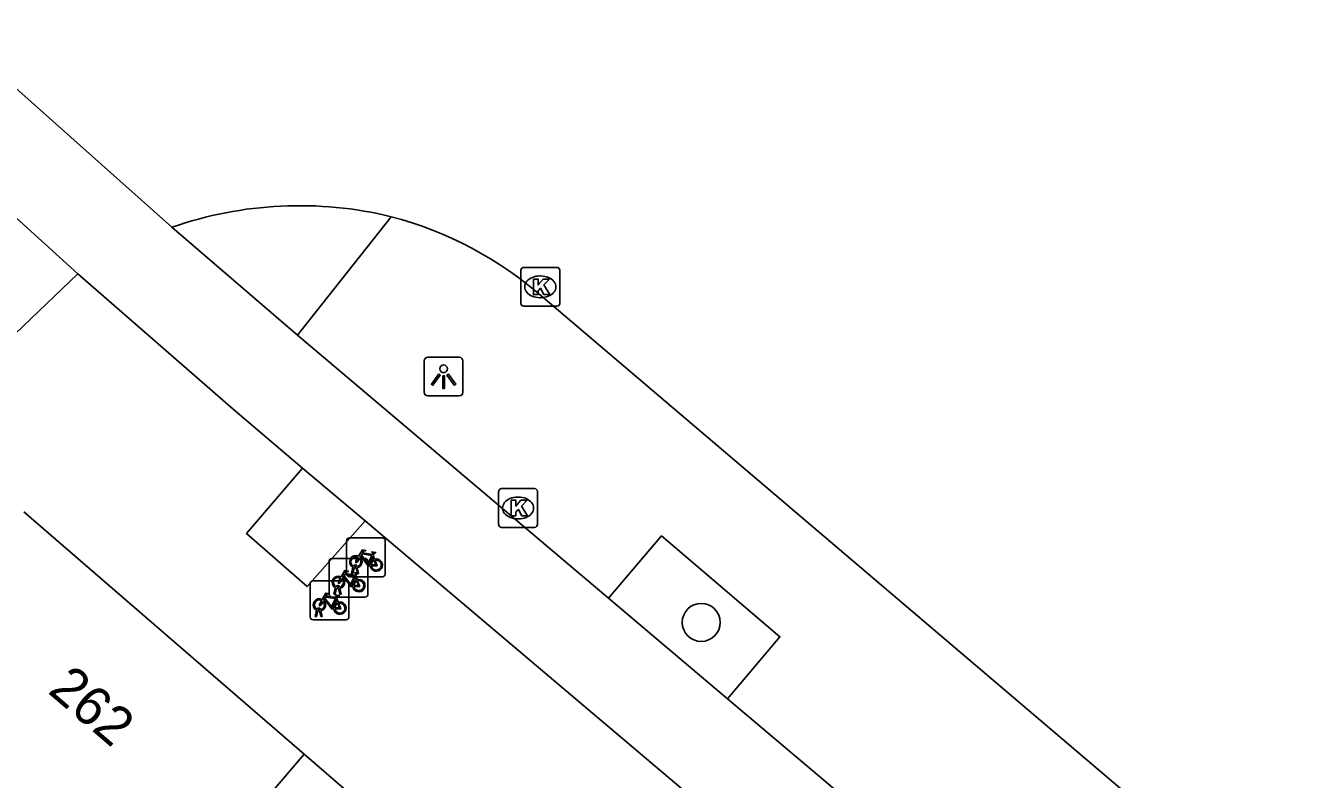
# Model space of a CAD drawing. Extents: x 162347 to 162868, y 381221 to 381813.
# Drawn here: x 162687 to 162719.68, y 381648.06 to 381667.49 of the extents above; entities that cross this region are included whole.
import ezdxf

# ---------------------------------------------------------------- set-up
doc = ezdxf.new("R2010")
doc.units = 0
for name, color, linetype in [('IMGEO_Berm_open', 7, 'Continuous'), ('IMGEO_Boom', 7, 'Continuous'), ('IMGEO_Fietsenrek', 7, 'Continuous'), ('IMGEO_Fietspad_gesloten', 7, 'Continuous'), ('IMGEO_Kolk', 7, 'Continuous'), ('IMGEO_Lichtpunt', 7, 'Continuous'), ('IMGEO_Pand', 7, 'Continuous'), ('IMGEO_Pand_nummerreeks', 7, 'Continuous'), ('IMGEO_Rijbaan_lokaal_gesloten', 7, 'Continuous'), ('IMGEO_Voetpad_open', 7, 'Continuous')]:
    doc.layers.add(name, color=color, linetype=linetype)

msp = doc.modelspace()

# ---------------------------------------------------------------- linework, layer by layer
at = {"layer": 'IMGEO_Berm_open'}
for points in [[(162696.427, 381662.56), (162694.013, 381659.509)], [(162702.028, 381652.737), (162703.396, 381654.339), (162706.444, 381651.742), (162705.095, 381650.146)]]:
    msp.add_lwpolyline(points, dxfattribs=at)
at = {"layer": 'IMGEO_Boom'}
msp.add_circle((162704.417, 381652.111), 0.489, dxfattribs=at)
at = {"layer": 'IMGEO_Fietsenrek'}
for p, q in [((162695.276, 381653.363), (162695.276, 381654.204)), ((162695.276, 381654.204), (162695.276, 381653.363)), ((162695.351, 381654.288), (162696.192, 381654.288)), ((162696.192, 381654.288), (162695.351, 381654.288)), ((162696.276, 381654.213), (162696.276, 381653.372)), ((162696.276, 381653.372), (162696.276, 381654.213)), ((162694.826, 381652.833), (162694.826, 381653.674)), ((162694.826, 381653.674), (162694.826, 381652.833)), ((162694.901, 381653.758), (162695.742, 381653.758)), ((162695.742, 381653.758), (162694.901, 381653.758)), ((162695.403, 381653.372), (162695.442, 381653.532)), ((162695.514, 381653.544), (162695.513, 381653.548)), ((162695.545, 381653.555), (162695.546, 381653.548)), ((162695.826, 381653.683), (162695.826, 381652.842)), ((162695.826, 381652.842), (162695.826, 381653.683)), ((162695.963, 381653.837), (162695.999, 381653.742)), ((162696.201, 381653.288), (162695.36, 381653.288)), ((162695.36, 381653.288), (162696.201, 381653.288)), ((162695.437, 381653.372), (162695.403, 381653.372)), ((162695.472, 381653.52), (162695.437, 381653.372)), ((162695.513, 381653.307), (162695.549, 381653.212)), ((162695.555, 381653.372), (162695.521, 381653.514)), ((162695.553, 381653.518), (162695.588, 381653.372)), ((162695.588, 381653.372), (162695.555, 381653.372)), ((162694.338, 381652.253), (162694.338, 381653.094)), ((162694.338, 381653.094), (162694.338, 381652.253)), ((162694.413, 381653.178), (162695.254, 381653.178)), ((162695.254, 381653.178), (162694.413, 381653.178)), ((162694.953, 381652.842), (162694.992, 381653.002)), ((162695.022, 381652.99), (162694.987, 381652.842)), ((162695.064, 381653.014), (162695.063, 381653.018)), ((162695.105, 381652.842), (162695.071, 381652.984)), ((162695.095, 381653.025), (162695.096, 381653.018)), ((162695.103, 381652.988), (162695.138, 381652.842)), ((162695.338, 381653.103), (162695.338, 381652.262)), ((162695.338, 381652.262), (162695.338, 381653.103)), ((162695.751, 381652.758), (162694.91, 381652.758)), ((162694.91, 381652.758), (162695.751, 381652.758)), ((162694.987, 381652.842), (162694.953, 381652.842)), ((162695.025, 381652.727), (162695.061, 381652.632)), ((162695.138, 381652.842), (162695.105, 381652.842)), ((162694.465, 381652.262), (162694.504, 381652.422)), ((162694.499, 381652.262), (162694.465, 381652.262)), ((162694.534, 381652.41), (162694.499, 381652.262)), ((162694.576, 381652.434), (162694.575, 381652.438)), ((162694.617, 381652.262), (162694.583, 381652.404)), ((162694.607, 381652.445), (162694.608, 381652.438)), ((162694.615, 381652.408), (162694.65, 381652.262)), ((162694.65, 381652.262), (162694.617, 381652.262)), ((162695.263, 381652.178), (162694.422, 381652.178)), ((162694.422, 381652.178), (162695.263, 381652.178))]:
    msp.add_line(p, q, dxfattribs=at)
for points in [[(162695.589, 381653.814), (162695.684, 381653.978), (162695.77, 381653.964), (162695.772, 381653.955), (162695.716, 381653.944), (162695.689, 381653.899), (162695.945, 381653.858)], [(162695.932, 381653.833), (162695.675, 381653.874), (162695.658, 381653.845), (162695.825, 381653.625), (162695.932, 381653.833)], [(162695.945, 381653.858), (162695.97, 381653.907), (162695.964, 381653.911), (162695.941, 381653.915), (162695.929, 381653.922), (162695.928, 381653.925), (162695.93, 381653.93), (162696.025, 381653.915), (162696.027, 381653.905), (162696.017, 381653.892), (162696.005, 381653.886), (162695.991, 381653.892), (162695.963, 381653.837)], [(162695.61, 381653.762), (162695.558, 381653.672), (162695.518, 381653.647), (162695.519, 381653.694), (162695.574, 381653.788)], [(162695.885, 381653.57), (162695.835, 381653.57), (162695.644, 381653.821), (162695.625, 381653.789)], [(162695.98, 381653.735), (162695.95, 381653.812), (162695.841, 381653.594), (162695.884, 381653.594)], [(162695.914, 381653.594), (162696.034, 381653.593), (162695.99, 381653.707)], [(162696.01, 381653.714), (162696.065, 381653.569), (162695.915, 381653.569)], [(162695.16, 381653.232), (162695.108, 381653.142), (162695.068, 381653.117), (162695.069, 381653.164), (162695.124, 381653.258)], [(162695.139, 381653.284), (162695.234, 381653.448), (162695.32, 381653.434), (162695.322, 381653.425), (162695.266, 381653.414), (162695.239, 381653.369), (162695.495, 381653.328)], [(162695.435, 381653.04), (162695.385, 381653.04), (162695.194, 381653.291), (162695.175, 381653.259)], [(162695.482, 381653.303), (162695.225, 381653.344), (162695.208, 381653.315), (162695.375, 381653.095), (162695.482, 381653.303)], [(162695.53, 381653.205), (162695.5, 381653.282), (162695.391, 381653.064), (162695.434, 381653.064)], [(162695.495, 381653.328), (162695.52, 381653.377), (162695.514, 381653.381), (162695.491, 381653.385), (162695.479, 381653.392), (162695.478, 381653.395), (162695.48, 381653.4), (162695.575, 381653.385), (162695.577, 381653.375), (162695.567, 381653.362), (162695.555, 381653.356), (162695.541, 381653.362), (162695.513, 381653.307)], [(162695.464, 381653.064), (162695.584, 381653.063), (162695.54, 381653.177)], [(162695.56, 381653.184), (162695.615, 381653.039), (162695.465, 381653.039)], [(162694.672, 381652.652), (162694.62, 381652.562), (162694.58, 381652.537), (162694.581, 381652.584), (162694.636, 381652.678)], [(162694.651, 381652.704), (162694.746, 381652.868), (162694.832, 381652.854), (162694.834, 381652.845), (162694.778, 381652.834), (162694.751, 381652.789), (162695.007, 381652.748)], [(162694.947, 381652.46), (162694.897, 381652.46), (162694.706, 381652.711), (162694.687, 381652.679)], [(162694.994, 381652.723), (162694.737, 381652.764), (162694.72, 381652.735), (162694.887, 381652.515), (162694.994, 381652.723)], [(162695.042, 381652.625), (162695.012, 381652.702), (162694.903, 381652.484), (162694.946, 381652.484)], [(162694.976, 381652.484), (162695.096, 381652.483), (162695.052, 381652.597)], [(162695.072, 381652.604), (162695.127, 381652.459), (162694.977, 381652.459)], [(162695.007, 381652.748), (162695.032, 381652.797), (162695.026, 381652.801), (162695.003, 381652.805), (162694.991, 381652.812), (162694.99, 381652.815), (162694.992, 381652.82), (162695.087, 381652.805), (162695.089, 381652.795), (162695.079, 381652.782), (162695.067, 381652.776), (162695.053, 381652.782), (162695.025, 381652.727)]]:
    msp.add_lwpolyline(points, dxfattribs=at)
for centre, radius, start, end in [((162695.354, 381654.21), 0.0779, 92.4484, 184.2845), ((162695.354, 381654.21), 0.0779, 92.4484, 184.2845), ((162696.198, 381654.21), 0.0779, 2.4484, 94.2845), ((162696.198, 381654.21), 0.0779, 2.4484, 94.2845), ((162694.904, 381653.68), 0.0779, 92.4484, 184.2845), ((162694.904, 381653.68), 0.0779, 92.4484, 184.2845), ((162695.516, 381653.673), 0.159, 62.6766, 242.1369), ((162695.516, 381653.673), 0.129, 63.3192, 238.903), ((162695.496, 381653.544), 0.0499, 12.8025, 158.6934), ((162695.496, 381653.544), 0.0174, 12.8025, 163.4502), ((162695.516, 381653.673), 0.129, 253.415, 269.0204), ((162695.516, 381653.673), 0.129, 283.6043, 43.4302), ((162695.516, 381653.673), 0.159, 283.5766, 46.6042), ((162695.748, 381653.68), 0.0779, 2.4484, 94.2845), ((162695.748, 381653.68), 0.0779, 2.4484, 94.2845), ((162696.043, 381653.589), 0.159, 113.3408, 178.3217), ((162696.043, 381653.589), 0.159, 187.0065, 105.7708), ((162696.043, 381653.589), 0.129, 113.923, 177.9556), ((162696.043, 381653.589), 0.129, 188.6715, 104.5883), ((162695.066, 381653.143), 0.159, 62.6766, 242.1369), ((162695.066, 381653.143), 0.129, 63.3192, 238.903), ((162695.066, 381653.143), 0.129, 283.6043, 43.4302), ((162695.066, 381653.143), 0.159, 283.5766, 46.6042), ((162695.354, 381653.366), 0.0779, 182.4484, 274.2845), ((162695.354, 381653.366), 0.0779, 182.4484, 274.2845), ((162695.593, 381653.059), 0.159, 113.3408, 178.3217), ((162695.593, 381653.059), 0.159, 187.0065, 105.7708), ((162695.516, 381653.673), 0.159, 253.9967, 271.7867), ((162696.198, 381653.366), 0.0779, 272.4484, 4.2845), ((162696.198, 381653.366), 0.0779, 272.4484, 4.2845), ((162694.416, 381653.1), 0.0779, 92.4484, 184.2845), ((162694.416, 381653.1), 0.0779, 92.4484, 184.2845), ((162695.046, 381653.014), 0.0499, 12.8025, 158.6934), ((162695.066, 381653.143), 0.159, 253.9967, 271.7867), ((162695.046, 381653.014), 0.0174, 12.8025, 163.4502), ((162695.066, 381653.143), 0.129, 253.415, 269.0204), ((162695.26, 381653.1), 0.0779, 2.4484, 94.2845), ((162695.26, 381653.1), 0.0779, 2.4484, 94.2845), ((162695.593, 381653.059), 0.129, 113.923, 177.9556), ((162695.593, 381653.059), 0.129, 188.6715, 104.5883), ((162694.578, 381652.563), 0.159, 62.6766, 242.1369), ((162694.578, 381652.563), 0.129, 63.3192, 238.903), ((162694.578, 381652.563), 0.129, 283.6043, 43.4302), ((162694.578, 381652.563), 0.159, 283.5766, 46.6042), ((162694.904, 381652.836), 0.0779, 182.4484, 274.2845), ((162694.904, 381652.836), 0.0779, 182.4484, 274.2845), ((162695.105, 381652.479), 0.159, 113.3408, 178.3217), ((162695.105, 381652.479), 0.159, 187.0065, 105.7708), ((162695.105, 381652.479), 0.129, 113.923, 177.9556), ((162695.105, 381652.479), 0.129, 188.6715, 104.5883), ((162695.748, 381652.836), 0.0779, 272.4484, 4.2845), ((162695.748, 381652.836), 0.0779, 272.4484, 4.2845), ((162694.416, 381652.256), 0.0779, 182.4484, 274.2845), ((162694.416, 381652.256), 0.0779, 182.4484, 274.2845), ((162694.558, 381652.434), 0.0499, 12.8025, 158.6934), ((162694.578, 381652.563), 0.159, 253.9967, 271.7867), ((162694.558, 381652.434), 0.0174, 12.8025, 163.4502), ((162694.578, 381652.563), 0.129, 253.415, 269.0204), ((162695.26, 381652.256), 0.0779, 272.4484, 4.2845), ((162695.26, 381652.256), 0.0779, 272.4484, 4.2845)]:
    msp.add_arc(centre, radius, start, end, dxfattribs=at)
at = {"layer": 'IMGEO_Fietspad_gesloten'}
for points in [[(162694.013, 381659.509), (162690.775, 381662.288)], [(162694.144, 381656.087), (162692.352, 381657.601), (162688.355, 381661.085)], [(162694.013, 381659.509), (162702.028, 381652.737)], [(162694.144, 381656.087), (162695.755, 381654.725)], [(162704.011, 381647.75), (162695.755, 381654.725)], [(162705.095, 381650.146), (162702.028, 381652.737)], [(162705.095, 381650.146), (162708.354, 381647.393), (162719.685, 381637.816)]]:
    msp.add_lwpolyline(points, dxfattribs=at)
at = {"layer": 'IMGEO_Kolk'}
for p, q in [((162699.771, 381660.328), (162699.771, 381661.18)), ((162699.846, 381661.254), (162700.698, 381661.254)), ((162700.772, 381661.18), (162700.772, 381660.328)), ((162700.259, 381661.034), (162700.284, 381661.034)), ((162700.282, 381660.474), (162700.257, 381660.474)), ((162700.698, 381660.254), (162699.846, 381660.254)), ((162699.272, 381655.558), (162700.124, 381655.558)), ((162699.197, 381654.632), (162699.197, 381655.484)), ((162699.685, 381655.338), (162699.71, 381655.338)), ((162700.198, 381655.484), (162700.198, 381654.632)), ((162700.124, 381654.558), (162699.272, 381654.558)), ((162699.708, 381654.778), (162699.683, 381654.778))]:
    msp.add_line(p, q, dxfattribs=at)
for points in [[(162699.771, 381660.328), (162699.771, 381661.18)], [(162699.846, 381661.254), (162700.698, 381661.254)], [(162700.772, 381661.18), (162700.772, 381660.328)], [(162700.092, 381660.954), (162700.215, 381660.954), (162700.215, 381660.803), (162700.345, 381660.954), (162700.509, 381660.954), (162700.363, 381660.803), (162700.516, 381660.554), (162700.364, 381660.554), (162700.279, 381660.718), (162700.215, 381660.651), (162700.215, 381660.554), (162700.092, 381660.554), (162700.092, 381660.954)], [(162700.698, 381660.254), (162699.846, 381660.254)], [(162699.272, 381655.558), (162700.124, 381655.558)], [(162699.197, 381654.632), (162699.197, 381655.484)], [(162699.518, 381655.258), (162699.641, 381655.258), (162699.641, 381655.107), (162699.771, 381655.258), (162699.935, 381655.258), (162699.789, 381655.107), (162699.942, 381654.858), (162699.79, 381654.858), (162699.705, 381655.022), (162699.641, 381654.955), (162699.641, 381654.858), (162699.518, 381654.858), (162699.518, 381655.258)], [(162700.198, 381655.484), (162700.198, 381654.632)], [(162700.124, 381654.558), (162699.272, 381654.558)]]:
    msp.add_lwpolyline(points, dxfattribs=at)
for centre, start, end in [((162699.848, 381661.178), 91.552, 178.448), ((162699.848, 381661.178), 91.552, 178.448), ((162700.696, 381661.178), 1.552, 88.448), ((162700.696, 381661.178), 1.552, 88.448), ((162699.848, 381660.33), 181.552, 268.448), ((162699.848, 381660.33), 181.552, 268.448), ((162700.696, 381660.33), 271.552, 358.448), ((162700.696, 381660.33), 271.552, 358.448), ((162699.274, 381655.482), 91.552, 178.448), ((162699.274, 381655.482), 91.552, 178.448), ((162700.122, 381655.482), 1.552, 88.448), ((162700.122, 381655.482), 1.552, 88.448), ((162699.274, 381654.634), 181.552, 268.448), ((162699.274, 381654.634), 181.552, 268.448), ((162700.122, 381654.634), 271.552, 358.448), ((162700.122, 381654.634), 271.552, 358.448)]:
    msp.add_arc(centre, 0.0765, start, end, dxfattribs=at)
for centre, major_axis, ratio, start_param, end_param in [((162700.258, 381660.754), (-0.387, 0.002), 0.722429, 4.712389, 7.853982), ((162700.283, 381660.754), (-0.39, 0.002), 0.717154, 1.570796, 4.712389), ((162699.684, 381655.058), (-0.387, 0.002), 0.722429, 4.712389, 7.853982), ((162699.709, 381655.058), (-0.39, 0.002), 0.717154, 1.570796, 4.712389)]:
    msp.add_ellipse(centre, major_axis=major_axis, ratio=ratio, start_param=start_param, end_param=end_param, dxfattribs=at)
at = {"layer": 'IMGEO_Lichtpunt'}
for p, q in [((162697.279, 381658.845), (162697.279, 381658.038)), ((162697.279, 381658.845), (162697.279, 381658.038)), ((162698.181, 381658.94), (162697.373, 381658.94)), ((162698.181, 381658.94), (162697.373, 381658.94)), ((162698.275, 381658.038), (162698.275, 381658.845)), ((162698.275, 381658.038), (162698.275, 381658.845)), ((162697.373, 381657.944), (162698.181, 381657.944)), ((162697.373, 381657.944), (162698.181, 381657.944))]:
    msp.add_line(p, q, dxfattribs=at)
for points in [[(162697.653, 381658.509), (162697.692, 381658.481), (162697.504, 381658.219), (162697.466, 381658.246), (162697.653, 381658.509)], [(162697.755, 381658.461), (162697.802, 381658.461), (162697.802, 381658.139), (162697.755, 381658.139), (162697.755, 381658.461)], [(162697.865, 381658.481), (162697.903, 381658.508), (162698.09, 381658.246), (162698.051, 381658.218), (162697.865, 381658.481)]]:
    msp.add_lwpolyline(points, dxfattribs=at)
msp.add_circle((162697.778, 381658.643), 0.0994, dxfattribs=at)
for centre, start, end in [((162697.373, 381658.845), 90, 180), ((162697.373, 381658.845), 90, 180), ((162698.181, 381658.845), 0, 90), ((162698.181, 381658.845), 0, 90), ((162697.373, 381658.038), 180, 270), ((162697.373, 381658.038), 180, 270), ((162698.181, 381658.038), 270, 0), ((162698.181, 381658.038), 270, 360)]:
    msp.add_arc(centre, 0.0946, start, end, dxfattribs=at)
at = {"layer": 'IMGEO_Pand'}
for points in [[(162686.96, 381654.957), (162694.188, 381648.719)], [(162675.845, 381641.49), (162682.884, 381635.503), (162694.188, 381648.719)], [(162694.188, 381648.719), (162700.183, 381643.545), (162700.101, 381642.634), (162699.87, 381642.371), (162701.463, 381641.084), (162701.664, 381641.32), (162702.596, 381641.595), (162708.391, 381636.674)]]:
    msp.add_lwpolyline(points, dxfattribs=at)
at = {"layer": 'IMGEO_Rijbaan_lokaal_gesloten'}
for points in [[(162684.935, 381667.487), (162690.775, 381662.288)], [(162684.232, 381664.825), (162688.355, 381661.085)], [(162688.355, 381661.085), (162685.311, 381658.19)], [(162700.335, 381660.484), (162718.383, 381645.147)]]:
    msp.add_lwpolyline(points, dxfattribs=at)
for centre, radius, start, end in [((162694.062, 381652.854), 9.99, 76.3033, 109.2071), ((162693.99, 381653.256), 9.618, 48.7216, 75.3223)]:
    msp.add_arc(centre, radius, start, end, dxfattribs=at)
at = {"layer": 'IMGEO_Voetpad_open'}
msp.add_lwpolyline([(162695.755, 381654.725), (162694.259, 381653.034), (162692.702, 381654.405), (162694.144, 381656.087)], dxfattribs=at)

# ---------------------------------------------------------------- texts
at = {"layer": 'IMGEO_Pand_nummerreeks'}
msp.add_text('262', height=1, rotation=319.469, dxfattribs=at).set_placement((162687.551, 381650.314))

doc.saveas('drawing.dxf')
